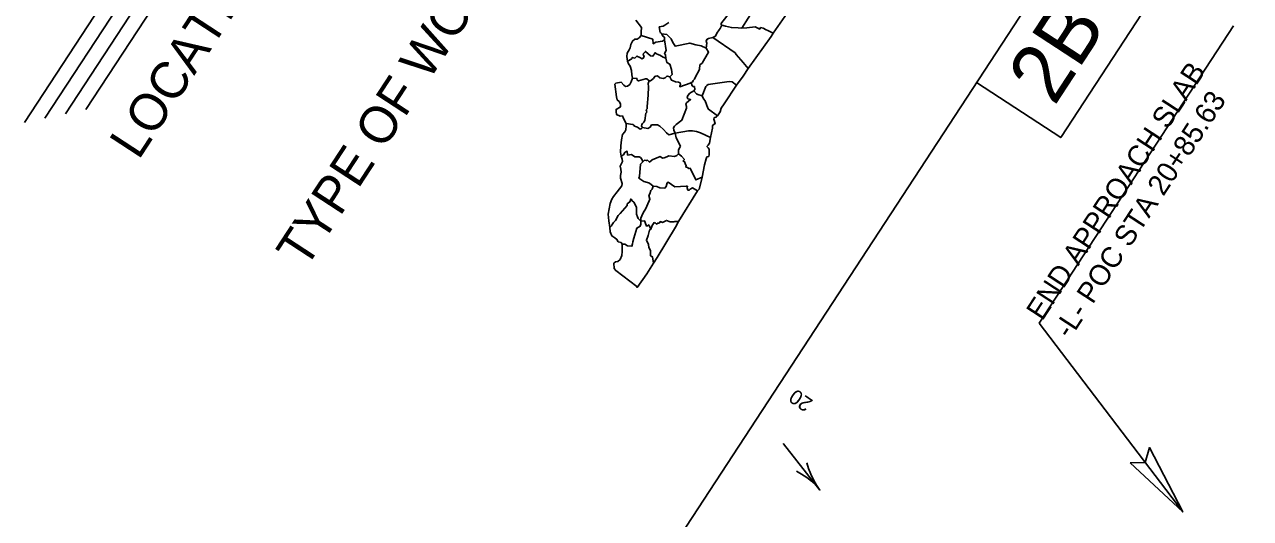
# Model space of a CAD drawing. Extents: x 1190029 to 2382315, y 163128 to 334830.
# Drawn here: x 2379630 to 2380460, y 332342 to 332677 of the extents above; entities that cross this region are included whole.
import ezdxf

# ---------------------------------------------------------------- set-up
doc = ezdxf.new("R2010")
doc.units = 0
for name, color, linetype in [('Exist Property Line', 7, 'Continuous'), ('Exist Utilities Telephone UG FO SUE LOS B Text', 7, 'Continuous'), ('P_NCDOT_Vertical_Profile_Grade_Sheet_Elevation_Label', 7, 'Continuous'), ('Sheet Block Title CELL', 7, 'Continuous'), ('Sheet_Plan_CELL', 7, 'Continuous'), ('Sheet_RDY_PE_Seal_Cell', 7, 'Continuous')]:
    doc.layers.add(name, color=color, linetype=linetype)

msp = doc.modelspace()

# ---------------------------------------------------------------- linework, layer by layer
at = {"layer": 'Exist Utilities Telephone UG FO SUE LOS B Text'}
for p, q in [((2379629.9, 332610.26), (2380096.14, 333323.37)), ((2379643.75, 332613.16), (2380099.04, 333309.53)), ((2379657.61, 332616.04), (2380101.91, 333295.7)), ((2379671.43, 332618.95), (2380104.83, 333281.85))]:
    msp.add_line(p, q, dxfattribs=at)
at = {"layer": 'Sheet Block Title CELL'}
msp.add_lwpolyline([(2380378.38, 332379.66), (2380413.98, 332346.42), (2380391.6, 332390.03), (2380388.51, 332379.98)], close=True, dxfattribs=at)
at = {"layer": 'Sheet_Plan_CELL'}
for p, q in [((2380316.89, 332474.38), (2380448.39, 332675.76)), ((2380413.98, 332346.42), (2380316.89, 332474.38)), ((2380156.02, 332376.91), (2380156.02, 332376.91))]:
    msp.add_line(p, q, dxfattribs=at)
msp.add_lwpolyline([(2379678.44, 331725.72), (2380382.48, 332802.63), (2380871.89, 332349.19), (2380229.4, 331365.52)], close=True, dxfattribs=at)
for points in [[(2380274.38, 332637.28), (2380331.45, 332599.97), (2380401.97, 332707.83)], [(2380159.62, 332379.74), (2380160.72, 332375.8), (2380162.16, 332371.91), (2380163.94, 332368.12), (2380165.98, 332364.51), (2380168.4, 332361.2), (2380143.64, 332392.61), (2380168.4, 332361.2), (2380165.75, 332364.33), (2380162.72, 332367.16), (2380159.45, 332369.77), (2380156, 332372.08), (2380152.43, 332374.07)]]:
    msp.add_lwpolyline(points, dxfattribs=at)
at = {"layer": 'Sheet_RDY_PE_Seal_Cell'}
for points in [[(2380101.4, 332677.01), (2380124.43, 332706.61), (2380125.02, 332706.34), (2380126.12, 332705.13), (2380126.91, 332704.68), (2380129.04, 332704.26), (2380130.45, 332703.14), (2380132.73, 332701.38), (2380115.52, 332674.15), (2380113.09, 332674.21), (2380108.47, 332674.49), (2380104.44, 332675.45), (2380102.03, 332676.09), (2380101.4, 332677.01)], [(2380147.7, 332686.54), (2380136.72, 332670.74), (2380133.23, 332672.58), (2380131.93, 332672.87), (2380130.07, 332674.13), (2380128.26, 332674.5), (2380127.62, 332673.49), (2380125.52, 332674.48), (2380124.59, 332675.05), (2380118.9, 332674.22), (2380115.52, 332674.15), (2380132.73, 332701.38)], [(2380037.19, 332607.85), (2380037.08, 332605.19), (2380036.22, 332603.88), (2380034.76, 332602.13), (2380034.1, 332598.39), (2380033.65, 332594.47), (2380033.31, 332590.12), (2380033.93, 332587.34), (2380034.47, 332585.46), (2380034.79, 332583.88), (2380033.86, 332582.04), (2380033.08, 332580.55), (2380033.5, 332578.66), (2380033.93, 332576.64), (2380033.35, 332574.39), (2380033.46, 332572.4), (2380034.59, 332568.97), (2380034.29, 332567.2), (2380031.18, 332563.15), (2380028.63, 332560.06), (2380027.44, 332558.33), (2380026.35, 332555.32), (2380025.59, 332551.7), (2380025.13, 332548.17), (2380025.49, 332543.51), (2380026.08, 332539.13), (2380026.48, 332536.09), (2380027.43, 332533.42), (2380029.53, 332532.17), (2380030.98, 332530.97), (2380031.9, 332529.4), (2380033.74, 332528.83), (2380034.55, 332527.69), (2380034.41, 332525.69), (2380034.56, 332522.75), (2380034.3, 332520.03), (2380033.13, 332517.46), (2380031.68, 332515.96), (2380030.09, 332515.85), (2380028.78, 332514.81), (2380029.18, 332511.2), (2380030.2, 332509.9), (2380044.44, 332499.08), (2380044.62, 332498.46), (2380051.21, 332507.68), (2380055.75, 332514.95), (2380058.15, 332518.72), (2380070.51, 332539.24), (2380072.73, 332543.04), (2380085.59, 332564), (2380086.71, 332565.07), (2380088.49, 332572.07), (2380088.59, 332573.17), (2380090.14, 332581.57), (2380091.29, 332585.57), (2380091.89, 332586.84), (2380093.13, 332587.22), (2380093.41, 332588.52), (2380093.51, 332592.11), (2380092.67, 332593.06), (2380091.85, 332593.88), (2380092.72, 332594.92), (2380093.7, 332596.22), (2380094.37, 332599.93), (2380095.66, 332606.45), (2380095.72, 332608.18), (2380097.47, 332609.43), (2380096.48, 332612.42), (2380096.74, 332613.27), (2380098.28, 332613.98), (2380098.98, 332614.81), (2380100.9, 332617.35), (2380101.54, 332619.91), (2380103.49, 332622.77), (2380111.95, 332635.46), (2380116.36, 332641.59), (2380119.89, 332646.81), (2380135.4, 332668.4), (2380136.72, 332670.74), (2380147.7, 332686.54)], [(2380043.86, 332679.43), (2380047.49, 332674.49), (2380047.37, 332671.56), (2380047.35, 332669.16), (2380045.99, 332667.43), (2380044.76, 332666.67), (2380043.15, 332666.6), (2380041.44, 332665.28), (2380040.38, 332662.92), (2380040.02, 332660.82), (2380039.23, 332659.32), (2380037.9, 332657.2), (2380037.62, 332654.9), (2380038.18, 332651.65), (2380038.82, 332650.02), (2380040.03, 332648.38), (2380040.84, 332645.42), (2380041.12, 332642.53), (2380041.42, 332640.23), (2380040.64, 332637.76), (2380039.63, 332635.86), (2380038.17, 332634.69), (2380036.83, 332634.51), (2380035.54, 332635.36), (2380033.77, 332637.46), (2380030.15, 332636.8), (2380029.56, 332636.1), (2380030.67, 332627.59), (2380031.16, 332625.5), (2380032.54, 332624.34), (2380033.31, 332622.73), (2380033.33, 332620.79), (2380030.38, 332619.09), (2380030.49, 332617.68), (2380030.58, 332615.68), (2380033.05, 332614.56), (2380034.64, 332614.78), (2380035.49, 332612.98), (2380037.12, 332609.46), (2380037.19, 332607.85)], [(2380065.99, 332677.92), (2380063.29, 332676.02), (2380062.23, 332675.48), (2380059.63, 332674.94), (2380060.34, 332671.18), (2380060.75, 332670.83), (2380061.38, 332670.17), (2380062.13, 332668.68), (2380063.27, 332667.94), (2380063.14, 332666.12), (2380061.72, 332665.29), (2380057.26, 332664.65), (2380055.6, 332663.53), (2380055.2, 332666.54), (2380047.35, 332669.16), (2380047.37, 332671.56), (2380047.49, 332674.49), (2380043.86, 332679.43)], [(2380101.4, 332677.01), (2380102.03, 332676.09), (2380100.96, 332673.89), (2380100.07, 332672.85), (2380098.55, 332670.67), (2380097.66, 332668.67), (2380095.93, 332667.75), (2380092.9, 332667.12), (2380091.79, 332666.51), (2380091.29, 332665.38), (2380091.9, 332664.01), (2380091.31, 332660.43), (2380087.94, 332662.01), (2380084.36, 332662.81), (2380080.3, 332664.02), (2380070.37, 332661.95), (2380068.63, 332664.77), (2380067.78, 332666.83), (2380064.76, 332669.68), (2380061.38, 332670.17), (2380060.75, 332670.83), (2380060.34, 332671.18), (2380059.63, 332674.94), (2380062.23, 332675.48), (2380063.29, 332676.02), (2380065.99, 332677.92)], [(2380102.03, 332676.09), (2380104.44, 332675.45), (2380108.47, 332674.49), (2380113.09, 332674.21), (2380115.52, 332674.15), (2380118.9, 332674.22), (2380124.59, 332675.05), (2380125.52, 332674.48), (2380127.62, 332673.49), (2380128.26, 332674.5), (2380130.07, 332674.13), (2380131.93, 332672.87), (2380133.23, 332672.58), (2380136.72, 332670.74), (2380135.4, 332668.4), (2380119.89, 332646.81), (2380116.49, 332650.82), (2380111.73, 332656.14), (2380110.95, 332657.29), (2380095.93, 332667.75), (2380097.66, 332668.67), (2380098.55, 332670.67), (2380100.07, 332672.85), (2380100.96, 332673.89), (2380102.03, 332676.09)], [(2380063.14, 332666.12), (2380064.35, 332659.05), (2380063.21, 332656.89), (2380063.86, 332655.98), (2380064.01, 332653.79), (2380062.23, 332654.48), (2380060.09, 332655.71), (2380058.29, 332656.53), (2380056.81, 332657.43), (2380055.37, 332655.17), (2380053.62, 332655.34), (2380050.19, 332658.28), (2380049, 332656.88), (2380048.68, 332655.95), (2380049.45, 332655.17), (2380049.02, 332653.97), (2380048.11, 332653.31), (2380046.5, 332654.2), (2380044.36, 332655.18), (2380043.11, 332653.84), (2380041.34, 332654.26), (2380041.15, 332653.34), (2380038.18, 332651.65), (2380037.62, 332654.9), (2380037.9, 332657.2), (2380039.23, 332659.32), (2380040.02, 332660.82), (2380040.38, 332662.92), (2380041.44, 332665.28), (2380043.15, 332666.6), (2380044.76, 332666.67), (2380045.99, 332667.43), (2380047.35, 332669.16), (2380055.2, 332666.54), (2380055.6, 332663.53), (2380057.26, 332664.65), (2380061.72, 332665.29), (2380063.14, 332666.12)], [(2380062.13, 332668.68), (2380061.38, 332670.17), (2380064.76, 332669.68), (2380067.78, 332666.83), (2380068.63, 332664.77), (2380070.37, 332661.95), (2380080.3, 332664.02), (2380084.36, 332662.81), (2380087.94, 332662.01), (2380091.31, 332660.43), (2380093.02, 332657.87), (2380088.68, 332650.43), (2380087.16, 332649.21), (2380086.85, 332646.35), (2380086.26, 332644.82), (2380084.54, 332641.98), (2380083.57, 332639.45), (2380082.68, 332638.54), (2380082.06, 332637.39), (2380081.29, 332637.32), (2380080.5, 332636.8), (2380073.51, 332634.39), (2380073.52, 332635.1), (2380073.97, 332635.91), (2380073.7, 332636.98), (2380072.69, 332637.6), (2380070.57, 332637.73), (2380068.51, 332638.65), (2380067.8, 332638.78), (2380066.86, 332641.14), (2380068.28, 332642.69), (2380067.84, 332646.19), (2380066.75, 332649.64), (2380064.75, 332650.76), (2380064.01, 332653.79), (2380063.86, 332655.98), (2380063.21, 332656.89), (2380064.35, 332659.05), (2380063.14, 332666.12), (2380063.27, 332667.94), (2380062.13, 332668.68)], [(2380095.93, 332667.75), (2380110.95, 332657.29), (2380111.73, 332656.14), (2380116.49, 332650.82), (2380119.89, 332646.81), (2380116.36, 332641.59), (2380111.95, 332635.46), (2380108.86, 332637.76), (2380106.93, 332637.98), (2380092.77, 332636.01), (2380091.86, 332635.35), (2380091.21, 332634.59), (2380088.6, 332628.32), (2380085.73, 332629.1), (2380084.93, 332629.54), (2380083.12, 332631.57), (2380083.69, 332632.52), (2380083.36, 332634.48), (2380082.39, 332634.59), (2380081.85, 332634.93), (2380081.29, 332637.32), (2380082.06, 332637.39), (2380082.68, 332638.54), (2380083.57, 332639.45), (2380084.54, 332641.98), (2380086.26, 332644.82), (2380086.85, 332646.35), (2380087.16, 332649.21), (2380088.68, 332650.43), (2380093.02, 332657.87), (2380091.31, 332660.43), (2380091.9, 332664.01), (2380091.29, 332665.38), (2380091.79, 332666.51), (2380092.9, 332667.12), (2380095.93, 332667.75)], [(2380038.18, 332651.65), (2380041.15, 332653.34), (2380041.34, 332654.26), (2380043.11, 332653.84), (2380044.36, 332655.18), (2380046.5, 332654.2), (2380048.11, 332653.31), (2380049.02, 332653.97), (2380049.45, 332655.17), (2380048.68, 332655.95), (2380049, 332656.88), (2380050.19, 332658.28), (2380053.62, 332655.34), (2380055.37, 332655.17), (2380056.81, 332657.43), (2380058.29, 332656.53), (2380060.09, 332655.71), (2380062.23, 332654.48), (2380064.01, 332653.79), (2380064.75, 332650.76), (2380066.75, 332649.64), (2380067.84, 332646.19), (2380068.28, 332642.69), (2380066.86, 332641.14), (2380065.16, 332641.51), (2380064.6, 332641.27), (2380063.57, 332640.47), (2380062.26, 332640.03), (2380059.97, 332640.54), (2380058.4, 332641.75), (2380057.38, 332641.66), (2380056.51, 332641.32), (2380055.7, 332640.09), (2380053.64, 332638.49), (2380052.87, 332638.42), (2380051.11, 332639.68), (2380050.4, 332639.68), (2380045.61, 332638.34), (2380044.67, 332638.91), (2380044.46, 332640.05), (2380041.42, 332640.23), (2380041.12, 332642.53), (2380040.84, 332645.42), (2380040.03, 332648.38), (2380038.82, 332650.02), (2380038.18, 332651.65)], [(2380030.67, 332627.59), (2380029.56, 332636.1), (2380030.15, 332636.8), (2380033.77, 332637.46), (2380035.54, 332635.36), (2380036.83, 332634.51), (2380038.17, 332634.69), (2380039.63, 332635.86), (2380040.64, 332637.76), (2380041.42, 332640.23), (2380044.46, 332640.05), (2380044.67, 332638.91), (2380045.61, 332638.34), (2380050.4, 332639.68), (2380051.11, 332639.68), (2380052.87, 332638.42), (2380052.11, 332636.54), (2380052.34, 332634.43), (2380052.01, 332628.59), (2380051.5, 332621), (2380051.36, 332619.44), (2380050.71, 332618.8), (2380050.9, 332618.04), (2380051.15, 332617.23), (2380050.56, 332616.53), (2380049.93, 332611.57), (2380049.18, 332610.4), (2380048.17, 332609.47), (2380047.78, 332608.72), (2380047.59, 332607.8), (2380048.38, 332606.78), (2380047.3, 332605.91), (2380046.6, 332605.78), (2380044.89, 332607.1), (2380042.92, 332607.68), (2380042.35, 332608.4), (2380041.68, 332608.73), (2380037.12, 332609.46), (2380035.49, 332612.98), (2380034.64, 332614.78), (2380033.05, 332614.56), (2380030.58, 332615.68), (2380030.49, 332617.68), (2380030.38, 332619.09), (2380033.33, 332620.79), (2380033.31, 332622.73), (2380032.54, 332624.34), (2380031.16, 332625.5), (2380030.67, 332627.59)], [(2380052.11, 332636.54), (2380052.87, 332638.42), (2380053.64, 332638.49), (2380055.7, 332640.09), (2380056.51, 332641.32), (2380057.38, 332641.66), (2380058.4, 332641.75), (2380059.97, 332640.54), (2380062.26, 332640.03), (2380063.57, 332640.47), (2380064.6, 332641.27), (2380065.16, 332641.51), (2380066.86, 332641.14), (2380067.8, 332638.78), (2380068.51, 332638.65), (2380070.57, 332637.73), (2380072.69, 332637.6), (2380073.7, 332636.98), (2380073.97, 332635.91), (2380073.52, 332635.1), (2380073.51, 332634.39), (2380080.5, 332636.8), (2380081.29, 332637.32), (2380081.85, 332634.93), (2380082.39, 332634.59), (2380083.36, 332634.48), (2380083.69, 332632.52), (2380083.12, 332631.57), (2380080.42, 332630.05), (2380079, 332628.51), (2380078.4, 332627.1), (2380079.04, 332626.2), (2380079.88, 332626.08), (2380080.81, 332625.65), (2380078.1, 332623.41), (2380077.65, 332622.6), (2380078.14, 332621.1), (2380078.03, 332620), (2380074.83, 332611.75), (2380071.15, 332608.9), (2380069.96, 332607.64), (2380069.34, 332606.62), (2380069.54, 332604.9), (2380070.4, 332602.86), (2380066, 332601.94), (2380064.55, 332603.28), (2380062.53, 332605.34), (2380060.04, 332607.68), (2380058.38, 332608.49), (2380054.46, 332608.58), (2380053.42, 332607.06), (2380051.97, 332606.03), (2380048.38, 332606.78), (2380047.59, 332607.8), (2380047.78, 332608.72), (2380048.17, 332609.47), (2380049.18, 332610.4), (2380049.93, 332611.57), (2380050.56, 332616.53), (2380051.15, 332617.23), (2380050.9, 332618.04), (2380050.71, 332618.8), (2380051.36, 332619.44), (2380051.5, 332621), (2380052.01, 332628.59), (2380052.34, 332634.43), (2380052.11, 332636.54)], [(2380088.6, 332628.32), (2380091.21, 332634.59), (2380091.86, 332635.35), (2380092.77, 332636.01), (2380106.93, 332637.98), (2380108.86, 332637.76), (2380111.95, 332635.46), (2380103.49, 332622.77), (2380101.54, 332619.91), (2380100.9, 332617.35), (2380098.98, 332614.81), (2380092.92, 332619.15), (2380092.41, 332619.94), (2380090.64, 332624.91), (2380089.59, 332626.17), (2380088.6, 332628.32)], [(2380088.6, 332628.32), (2380089.59, 332626.17), (2380090.64, 332624.91), (2380092.41, 332619.94), (2380092.92, 332619.15), (2380098.98, 332614.81), (2380098.28, 332613.98), (2380096.74, 332613.27), (2380096.48, 332612.42), (2380097.47, 332609.43), (2380095.72, 332608.18), (2380095.66, 332606.45), (2380094.37, 332599.93), (2380087.44, 332603.08), (2380084.93, 332604.13), (2380082.22, 332604.53), (2380079.48, 332604.47), (2380070.4, 332602.86), (2380069.54, 332604.9), (2380069.34, 332606.62), (2380069.96, 332607.64), (2380071.15, 332608.9), (2380074.83, 332611.75), (2380078.03, 332620), (2380078.14, 332621.1), (2380077.65, 332622.6), (2380078.1, 332623.41), (2380080.81, 332625.65), (2380079.88, 332626.08), (2380079.04, 332626.2), (2380078.4, 332627.1), (2380079, 332628.51), (2380080.42, 332630.05), (2380083.12, 332631.57), (2380084.93, 332629.54), (2380085.73, 332629.1), (2380088.6, 332628.32)], [(2380037.12, 332609.46), (2380041.68, 332608.73), (2380042.35, 332608.4), (2380042.92, 332607.68), (2380044.89, 332607.1), (2380046.6, 332605.78), (2380047.3, 332605.91), (2380048.38, 332606.78), (2380051.97, 332606.03), (2380053.42, 332607.06), (2380054.46, 332608.58), (2380058.38, 332608.49), (2380060.04, 332607.68), (2380062.53, 332605.34), (2380064.55, 332603.28), (2380066, 332601.94), (2380070.4, 332602.86), (2380071.02, 332599.84), (2380073.9, 332594.2), (2380073.65, 332593.21), (2380072.64, 332591.58), (2380072.53, 332588.94), (2380071.41, 332587.74), (2380069.99, 332587.16), (2380065.99, 332587.68), (2380064.76, 332587.04), (2380062.91, 332586.23), (2380061.89, 332586.13), (2380060.22, 332587.06), (2380054.83, 332584.93), (2380053.1, 332583.42), (2380051.72, 332584.57), (2380050.97, 332584.37), (2380049.67, 332584.63), (2380048.41, 332583.54), (2380047.74, 332585.4), (2380046.83, 332586.41), (2380045.94, 332587.03), (2380043.13, 332587.02), (2380040.83, 332588.47), (2380038.22, 332588.15), (2380038.03, 332588.9), (2380037.97, 332590.38), (2380037.69, 332590.74), (2380036.21, 332589.95), (2380035.38, 332588.38), (2380033.93, 332587.34), (2380033.31, 332590.12), (2380033.65, 332594.47), (2380034.1, 332598.39), (2380034.76, 332602.13), (2380036.22, 332603.88), (2380037.08, 332605.19), (2380037.19, 332607.85), (2380037.12, 332609.46)], [(2380070.4, 332602.86), (2380079.48, 332604.47), (2380082.22, 332604.53), (2380084.93, 332604.13), (2380087.44, 332603.08), (2380094.37, 332599.93), (2380093.7, 332596.22), (2380092.72, 332594.92), (2380091.85, 332593.88), (2380092.67, 332593.06), (2380093.51, 332592.11), (2380093.41, 332588.52), (2380093.13, 332587.22), (2380091.89, 332586.84), (2380091.29, 332585.57), (2380090.14, 332581.57), (2380088.59, 332573.17), (2380084.48, 332571.31), (2380080.52, 332579.25), (2380079.57, 332579.1), (2380078.83, 332579.6), (2380077.65, 332580), (2380077.75, 332581.1), (2380076.99, 332582.69), (2380077.14, 332583.16), (2380075.78, 332584.18), (2380076.66, 332585.22), (2380074.64, 332587.28), (2380072.53, 332588.94), (2380072.64, 332591.58), (2380073.65, 332593.21), (2380073.9, 332594.2), (2380071.02, 332599.84), (2380070.4, 332602.86)], [(2380040.31, 332558.29), (2380039.65, 332556.36), (2380037.98, 332555.03), (2380037.88, 332553.93), (2380036.25, 332552.09), (2380033.23, 332548.56), (2380031.69, 332547.25), (2380030.08, 332543.73), (2380028.72, 332542.5), (2380027.82, 332541.12), (2380027.34, 332540.1), (2380026.08, 332539.13), (2380025.49, 332543.51), (2380025.13, 332548.17), (2380025.59, 332551.7), (2380026.35, 332555.32), (2380027.44, 332558.33), (2380028.63, 332560.06), (2380031.18, 332563.15), (2380034.29, 332567.2), (2380034.59, 332568.97), (2380033.46, 332572.4), (2380033.35, 332574.39), (2380033.93, 332576.64), (2380033.5, 332578.66), (2380033.08, 332580.55), (2380033.86, 332582.04), (2380034.79, 332583.88), (2380034.47, 332585.46), (2380033.93, 332587.34), (2380035.38, 332588.38), (2380036.21, 332589.95), (2380037.69, 332590.74), (2380037.97, 332590.38), (2380038.03, 332588.9), (2380038.22, 332588.15), (2380040.83, 332588.47), (2380043.13, 332587.02), (2380045.94, 332587.03), (2380046.83, 332586.41), (2380047.74, 332585.4), (2380048.41, 332583.54), (2380046.82, 332581.9), (2380046.29, 332573.68), (2380045.68, 332572.53), (2380049.07, 332570.29), (2380051.63, 332569.58), (2380053.02, 332569.01), (2380055.42, 332567.13), (2380054.77, 332564.95), (2380054.02, 332564.04), (2380053.19, 332561.78), (2380052.57, 332560.75), (2380053.3, 332558.26), (2380052.75, 332557.18), (2380050.31, 332551.41), (2380048.89, 332549.4), (2380047.84, 332546.86), (2380047.13, 332545.44), (2380047.25, 332543.46), (2380045.37, 332545.13), (2380044.82, 332546.29), (2380044.15, 332548.15), (2380044.15, 332550.27), (2380044.14, 332552.64), (2380043.48, 332554.25), (2380042.29, 332556.18), (2380041.19, 332557.1), (2380040.57, 332558.32), (2380040.31, 332558.29)], [(2380046.82, 332581.9), (2380048.41, 332583.54), (2380049.67, 332584.63), (2380050.97, 332584.37), (2380051.72, 332584.57), (2380053.1, 332583.42), (2380054.83, 332584.93), (2380060.22, 332587.06), (2380061.89, 332586.13), (2380062.91, 332586.23), (2380064.76, 332587.04), (2380065.99, 332587.68), (2380069.99, 332587.16), (2380071.41, 332587.74), (2380072.53, 332588.94), (2380074.64, 332587.28), (2380076.66, 332585.22), (2380075.78, 332584.18), (2380077.14, 332583.16), (2380076.99, 332582.69), (2380077.75, 332581.1), (2380077.65, 332580), (2380078.83, 332579.6), (2380079.57, 332579.1), (2380080.52, 332579.25), (2380084.48, 332571.31), (2380088.59, 332573.17), (2380088.49, 332572.07), (2380086.71, 332565.07), (2380085.59, 332564), (2380082.13, 332565.84), (2380080.59, 332565.11), (2380079.96, 332564.35), (2380079.06, 332564.39), (2380078.61, 332565.95), (2380078.71, 332567.04), (2380077.76, 332567.01), (2380070.15, 332566.53), (2380065.61, 332569.74), (2380065.08, 332569.24), (2380064.25, 332566.85), (2380063.45, 332565.75), (2380059.98, 332566.04), (2380057.94, 332566.8), (2380055.42, 332567.13), (2380053.02, 332569.01), (2380051.63, 332569.58), (2380049.07, 332570.29), (2380045.68, 332572.53), (2380046.29, 332573.68), (2380046.82, 332581.9)], [(2380093.41, 332588.52), (2380093.13, 332587.22), (2380091.89, 332586.84), (2380091.29, 332585.57), (2380090.14, 332581.57), (2380088.59, 332573.17), (2380088.49, 332572.07)], [(2380054.77, 332564.95), (2380055.42, 332567.13), (2380057.94, 332566.8), (2380059.98, 332566.04), (2380063.45, 332565.75), (2380064.25, 332566.85), (2380065.08, 332569.24), (2380065.61, 332569.74), (2380070.15, 332566.53), (2380077.76, 332567.01), (2380078.71, 332567.04), (2380078.61, 332565.95), (2380079.06, 332564.39), (2380079.96, 332564.35), (2380080.59, 332565.11), (2380082.13, 332565.84), (2380085.59, 332564), (2380072.73, 332543.04), (2380070.23, 332543.24), (2380069.56, 332542.85), (2380067, 332542.98), (2380064.44, 332543.81), (2380061.75, 332542.51), (2380060.43, 332543.02), (2380059.5, 332542.02), (2380058.73, 332542.07), (2380057.83, 332541.41), (2380056.86, 332542.33), (2380056.09, 332542.38), (2380054.86, 332540.33), (2380053.93, 332537.93), (2380053.15, 332539.52), (2380052.33, 332540.91), (2380051.55, 332540.25), (2380051.06, 332540.07), (2380050.68, 332540.74), (2380049.52, 332543.69), (2380047.25, 332543.46), (2380047.13, 332545.44), (2380047.84, 332546.86), (2380048.89, 332549.4), (2380050.31, 332551.41), (2380052.75, 332557.18), (2380053.3, 332558.26), (2380052.57, 332560.75), (2380053.19, 332561.78), (2380054.02, 332564.04), (2380054.77, 332564.95)], [(2380047.25, 332543.46), (2380047.17, 332541.4), (2380046.61, 332539.87), (2380044.48, 332538.68), (2380042.29, 332531.78), (2380041.67, 332529.47), (2380041.47, 332528.1), (2380041.12, 332526.4), (2380038.04, 332526.59), (2380036.39, 332527.82), (2380034.55, 332527.69), (2380033.74, 332528.83), (2380031.9, 332529.4), (2380030.98, 332530.97), (2380029.53, 332532.17), (2380027.43, 332533.42), (2380026.48, 332536.09), (2380026.08, 332539.13), (2380027.34, 332540.1), (2380027.82, 332541.12), (2380028.72, 332542.5), (2380030.08, 332543.73), (2380031.69, 332547.25), (2380033.23, 332548.56), (2380036.25, 332552.09), (2380037.88, 332553.93), (2380037.98, 332555.03), (2380039.65, 332556.36), (2380040.31, 332558.29), (2380040.57, 332558.32), (2380041.19, 332557.1), (2380042.29, 332556.18), (2380043.48, 332554.25), (2380044.14, 332552.64), (2380044.15, 332550.27), (2380044.15, 332548.15), (2380044.82, 332546.29), (2380045.37, 332545.13), (2380047.25, 332543.46)], [(2380047.25, 332543.46), (2380049.52, 332543.69), (2380050.68, 332540.74), (2380051.06, 332540.07), (2380051.55, 332540.25), (2380052.33, 332540.91), (2380053.15, 332539.52), (2380053.93, 332537.93), (2380053.09, 332537.33), (2380052.2, 332533.71), (2380050.9, 332530.44), (2380052.38, 332527.46), (2380052.61, 332525.62), (2380053.76, 332523.5), (2380053.58, 332522.72), (2380053.64, 332519.97), (2380054.04, 332519.76), (2380054.98, 332519.22), (2380055.75, 332514.95), (2380051.21, 332507.68), (2380044.62, 332498.46), (2380044.44, 332499.08), (2380030.2, 332509.9), (2380029.18, 332511.2), (2380028.78, 332514.81), (2380030.09, 332515.85), (2380031.68, 332515.96), (2380033.13, 332517.46), (2380034.3, 332520.03), (2380034.56, 332522.75), (2380034.41, 332525.69), (2380034.55, 332527.69), (2380036.39, 332527.82), (2380038.04, 332526.59), (2380041.12, 332526.4), (2380041.47, 332528.1), (2380041.67, 332529.47), (2380042.29, 332531.78), (2380044.48, 332538.68), (2380046.61, 332539.87), (2380047.17, 332541.4), (2380047.25, 332543.46)], [(2380056.09, 332542.38), (2380056.86, 332542.33), (2380057.83, 332541.41), (2380058.73, 332542.07), (2380059.5, 332542.02), (2380060.43, 332543.02), (2380061.75, 332542.51), (2380064.44, 332543.81), (2380067, 332542.98), (2380069.56, 332542.85), (2380070.23, 332543.24), (2380072.73, 332543.04), (2380070.51, 332539.24), (2380058.15, 332518.72), (2380055.75, 332514.95), (2380054.98, 332519.22), (2380054.04, 332519.76), (2380053.64, 332519.97), (2380053.58, 332522.72), (2380053.76, 332523.5), (2380052.61, 332525.62), (2380052.38, 332527.46), (2380050.9, 332530.44), (2380052.2, 332533.71), (2380053.09, 332537.33), (2380053.93, 332537.93), (2380054.86, 332540.33), (2380056.09, 332542.38)]]:
    msp.add_lwpolyline(points, dxfattribs=at)

# ---------------------------------------------------------------- texts
at = {"layer": 'Exist Property Line'}
msp.add_text('20', height=10, rotation=145.37984, dxfattribs=at).set_placement((2380164.24, 332421.76))
at = {"layer": 'Exist Utilities Telephone UG FO SUE LOS B Text'}
for s, height, p in [('LOCATION: ', 25, (2379707.11, 332584.16)), ('TYPE OF WORK:', 25.0002, (2379820.12, 332510.28))]:
    msp.add_text(s, height=height, rotation=56.82484, dxfattribs=at).set_placement(p)
at = {"layer": 'P_NCDOT_Vertical_Profile_Grade_Sheet_Elevation_Label'}
msp.add_text('2B-1', height=40, rotation=56.82483, dxfattribs=at).set_placement((2380327.05, 332620.72))
at = {"layer": 'Sheet_Plan_CELL'}
for s, p in [('END APPROACH SLAB', (2380318.92, 332475.34)), ('-L- POC STA 20+85.63', (2380337.67, 332463.08))]:
    msp.add_text(s, height=14.0001, rotation=56.82483, dxfattribs=at).set_placement(p)

doc.saveas('drawing.dxf')
